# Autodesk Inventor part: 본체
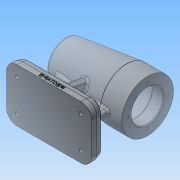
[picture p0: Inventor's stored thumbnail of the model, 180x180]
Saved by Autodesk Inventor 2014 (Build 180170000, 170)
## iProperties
Created: 2017-01
Part Number: 본체
Material: 일반
Document SubType Name: Modeling
Designer: nert
Density: 1 g/cm^3
Appearance: 기본값
Author: nert
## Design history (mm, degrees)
sketch "스케치1"
  geometry: L1 (-56, -35)-(56, -35); L2 (56, -35)-(56, 35); L3 (56, 35)-(-56, 35); L4 (-56, 35)-(-56, -35); L5 (-56, -35)-(56, 35); L6 (56, -35)-(-56, 35); 1 further point
  constraints: 12 end point, 2 horizontal, 2 midpoint, 2 vertical
  dimensions: "d0" = 112 distance of L2.end L3.end; "d1" = 70 distance of L1.end L2.end
extrude "돌출1" new body sketch "스케치1" distance "d2" = 14; taper "d3" = 0 deg
node "작업 평면1"
sketch "스케치2"
  geometry: L1 (112, 0)-(0, 0) reference; L2 (0, 0)-(0, 14) reference; L3 (112, 14)-(0, 14) reference; L4 (112, 0)-(112, 14) reference; L5 (112, 108)-(112, 74); L6 (112, 74)-(0, 74); L7 (112, 108)-(84, 108); L8 (84, 108)-(3.73, 98.144); L9 (112, 95)-(97, 95); L10 (97, 95)-(97, 98); L11 (97, 98)-(43, 98); L12 (43, 98)-(43, 95); L13 (43, 95)-(31, 95); L14 (31, 95)-(31, 91.5); L15 (31, 91.5)-(13, 91.5); L16 (13, 91.5)-(13, 90); L17 (13, 90)-(9, 90); L18 (9, 90)-(9, 84.5); L19 (9, 84.5)-(6, 84.5); L20 (6, 84.5)-(6, 74); A1 r 80 centre (80, 74) between (3.73, 98.144) and (0, 74); 4 further points
  constraints: 32 end point, 6 parallel, 3 midpoint, 2 point on circle, 2 point on line, 2 vertical alignment, 1 centre point, 1 horizontal, 1 tangent, 1 vertical
  dimensions: "d4" = 74 distance between parallel lines of L6 L1; "d6" = 28 distance of L5.start L7.end; "d7" = 7 deg angle of L7 L8; "d8" = 80 radius of A1; "d9" = 112 distance from line of L6.end L5; "d10" = 21 diameter of L19 L6; "d11" = 32 diameter of L17 L6; "d13" = 35 diameter of L15 L6; "d14" = 42 diameter of L13 L6; "d15" = 48 diameter of L11 L6; "d16" = 42 diameter of L9 L6; "d17" = 15 distance of L9.start L9.end; "d18" = 54 distance of L10.end L11.end; "d19" = 18 distance of L14.end L15.end; "d20" = 12 distance of L12.end L13.end; "d21" = 4 distance of L16.end L17.end; "d22" = 3 distance of L18.end L19.end; "d23" = 68 diameter of L7 L6
  node "투영된 루프1"
revolve "회전1" stored, may be unused: angle "d24" = 90 deg
sketch "스케치3"
  geometry: L1 (112, 0)-(0, 0) reference; L2 (0, 0)-(0, 14) reference; L3 (112, 14)-(0, 14) reference; L4 (112, 0)-(112, 14) reference; L5 (18, 74)-(18, 10.118); L6 (18, 10.118)-(94, 10.118); L7 (94, 10.118)-(94, 74); L8 (94, 74)-(18, 74); L9 (84, 40)-(84, 108) reference; L10 (112, 40)-(112, 108) reference; 4 further points
  constraints: 8 end point, 3 midpoint, 2 horizontal, 1 horizontal alignment, 1 vertical alignment
  dimensions: "d25" = 90 deg angle of L5 L3; "d26" = 90 deg angle of L3 L7; "d27" = 18 horizontal distance of L5.end L2.end; "d28" = 18 distance from line of L4 L6.end
extrude "돌출2" join sketch "스케치3" stored distance "d29" = 8; taper "d30" = 0 deg
node "작업 평면2"
sketch "스케치4"
  geometry: L1 (70, 0)-(0, 0) reference; L2 (0, 0)-(0, 14) reference; L3 (70, 14)-(0, 14) reference; L4 (70, 0)-(70, 14) reference; L5 (12, 14)-(22.58, 74); L6 (22.58, 74)-(47.42, 74); L7 (47.42, 74)-(58, 14); L8 (58, 14)-(12, 14); C1 r 34 at (35, 74) reference; 4 further points
  constraints: 8 end point, 3 midpoint, 1 coincident, 1 horizontal, 1 horizontal alignment, 1 vertical alignment
  dimensions: "d31" = 100 deg angle of L5 L3; "d32" = 100 deg angle of L3 L7; "d33" = 12 distance from line of L5.start L2; "d34" = 12 distance of L3.start L7.end; "d37" = 14 distance between parallel lines of L1 L8
extrude "돌출3" join sketch "스케치4" stored distance "d38" = 8; taper "d39" = 0 deg
sketch "스케치5"
  geometry: L1 (56, 35)-(-56, 35) reference; L2 (-56, 35)-(-56, -35) reference; L3 (-39.113, -26)-(-44.887, -26); L4 (-44.887, -26)-(-47.774, -21); L5 (-47.774, -21)-(-44.887, -16); L6 (-44.887, -16)-(-39.113, -16); L7 (-39.113, -16)-(-36.226, -21); L8 (-36.226, -21)-(-39.113, -26); L9 (-39.113, 16)-(-44.887, 16); L10 (-44.887, 16)-(-47.774, 21); L11 (-47.774, 21)-(-44.887, 26); L12 (-44.887, 26)-(-39.113, 26); L13 (-39.113, 26)-(-36.226, 21); L14 (-36.226, 21)-(-39.113, 16); C1 r 5 at (-42, 21); C2 r 5 at (-42, -21); 3 further points
  constraints: 24 end point, 2 centre point, 2 coincident, 2 horizontal, 1 equal radius, 1 parallel, 1 tangent, 1 vertical alignment, 26 other
  dimensions: "d40" = 42 distance of point (-42, 21) point (-42, -21); "d41" = 10 diameter of C1; "d42" = 14 distance from line of point (-42, 21) L2; "d43" = 14 distance from line of point (-42, 21) L1
extrude "돌출4" cut sketch "스케치5" distance "d44" = 4; taper "d45" = 0 deg
sketch "스케치6"
  geometry: L1 (-56, 35)-(-56, -35) reference; L2 (-56, -35)-(56, -35) reference; C1 r 2.5 at (-42, -21); 1 further point
  constraints: 1 centre point
  dimensions: "d46" = 5 diameter of C1; "d47" = 14 distance from line of L1 C1.centre; "d48" = 14 distance from line of L2 C1.centre
extrude "돌출5" cut sketch "스케치6" stored distance "d49" = 4; taper "d50" = 0 deg
revolve "회전2" stored, may be unused: angle "d51" = 90 deg
sketch "스케치7"
  geometry: C1 r 21 at (0, 0) reference; 2 further points
  constraints: 1 horizontal alignment
  dimensions: "d52" = 26 distance of C1.centre point (-26, 0)
hole "구멍1" sketch "스케치7" at (-26, 0) diameter "d53" = 3.242; stored, may be unused: countersink angle "d57" = 90 deg, drill point angle "d59" = 118 deg; dims "d54" = 8, "d55" = 4, "d56" = 2, "d58" = 11
fillet "모깎기1" dims "d78" = 14
chamfer "모따기6" distance "d79" = 7; stored, may be unused: second distance "d80" = 2, angle "d81" = 15 deg
fillet "모깎기2" dims "d82" = 1
sketch "스케치8"
  geometry: L1 (0, 0)-(84, 0) reference; L2 (98, 0)-(98, 7) reference; 2 further points
  constraints: 1 other
  dimensions: "d83" = 4 distance from line of L1 point (42, 4); "d84" = 56 distance from line of L2 point (42, 4)
feature "엠보싱1" sketch "스케치8" dims "d85" = 0.5, "d86" = 0
fillet "모깎기3" dims "d87" = 3
fillet "모깎기4" dims "d88" = 3
fillet "모깎기5" dims "d89" = 3
fillet "모깎기6" dims "d90" = 3
chamfer "모따기7" distance "d91" = 1; stored, may be unused: second distance "d92" = 2, angle "d93" = 15 deg
fillet "모깎기7" dims "d94" = 0.3
fillet "모깎기8" dims "d95" = 3
fillet "모깎기9" dims "d96" = 3
fillet "모깎기10" dims "d97" = 3
chamfer "모따기2" distance "d66" = 7; stored, may be unused: second distance "d67" = 2, angle "d68" = 15 deg
chamfer "모따기3" distance "d69" = 7; stored, may be unused: second distance "d70" = 2, angle "d71" = 15 deg
chamfer "모따기4" distance "d72" = 7; stored, may be unused: second distance "d73" = 2, angle "d74" = 15 deg
chamfer "모따기5" distance "d75" = 7; stored, may be unused: second distance "d76" = 2, angle "d77" = 15 deg
node "솔리드1"
mirror "대칭1"
mirror "대칭2"
pattern_circular "원형 패턴1" dims angle "d61" = 360 deg
node "투영된 루프2"
node "투영된 루프3"
node "투영된 루프4"
node "투영된 루프5"
